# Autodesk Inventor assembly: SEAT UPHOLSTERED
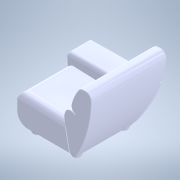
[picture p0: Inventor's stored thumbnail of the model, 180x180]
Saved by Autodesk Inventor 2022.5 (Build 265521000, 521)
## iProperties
Created: 2025-08
Part Number: SEAT UPHOLSTERED
Material: Generic
Document SubType Name: Modeling
Designer: Mark.Glazzard
Density: 1 g/cm^3
Appearance: Default
Author: Mark.Glazzard
Revision Number: ANY
Part Number: 1SG-0001 Arm Subassembly_UPHOLSTERED
Document SubType Name: Assembly
Part Number: ARM UPHOLSTERED
Part Number: 1SG-0001 Seat Subassembly_UPHOLSTERED
Part Number: 1SG-0001 Snug with Right Arm_Upholstered
Description: STEP AP214
Title: 1SG-0001 Snug with Right Arm_Upholstered.STEP
Sending System: SolidWorks 2025
Preprocessor: SwSTEP 2.0
Part Number: 1SG-0001 Back Subassembly_UPHOLSTERED
Part Number: BACK UPHOLSTERED
Part Number: PCM5592 - Snug Feet (Rev E)
Part Number: 1SG-0001 Snug with Right Arm (Simplify) 2022
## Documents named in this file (9)
- **S:\DRAWINGS\DRAWING OFFICE ONLY\WIP\1298 Snug with Arm\1SG-0001-01 Snug with Right Arm\Marketing and Sales Files\Simplified Inventor\1SG-0001 Snug with Right Arm (Simplify) 2022.iam*LocalDocs*xAaaaqebaAaaaaaaaAaaaapvl5e*SEAT UPHOLSTERED.ipt
- **S:\DRAWINGS\DRAWING OFFICE ONLY\WIP\1298 Snug with Arm\1SG-0001-01 Snug with Right Arm\Marketing and Sales Files\Simplified Inventor\1SG-0001 Snug with Right Arm (Simplify) 2022.iam*LocalDocs*xAaaaq0aaAaaaaaaaAaaaqzquAf*1SG-0001 Arm Subassembly_UPHOLSTERED.iam
- **S:\DRAWINGS\DRAWING OFFICE ONLY\WIP\1298 Snug with Arm\1SG-0001-01 Snug with Right Arm\Marketing and Sales Files\Simplified Inventor\1SG-0001 Snug with Right Arm (Simplify) 2022.iam*LocalDocs*xAaaaadaaAaaaaaaaAaaaqlp0Ea*ARM UPHOLSTERED.ipt
- **S:\DRAWINGS\DRAWING OFFICE ONLY\WIP\1298 Snug with Arm\1SG-0001-01 Snug with Right Arm\Marketing and Sales Files\Simplified Inventor\1SG-0001 Snug with Right Arm (Simplify) 2022.iam*LocalDocs*xAaaaq3caAaaaaaaaAaaaa3sn1a*1SG-0001 Seat Subassembly_UPHOLSTERED.iam
- **S:\DRAWINGS\DRAWING OFFICE ONLY\WIP\1298 Snug with Arm\1SG-0001-01 Snug with Right Arm\Marketing and Sales Files\Simplified Inventor\1SG-0001 Snug with Right Arm (Simplify) 2022.iam*LocalDocs*xAaaaq1caAaaaaaaaAaaaanuyJe*1SG-0001 Snug with Right Arm_Upholstered.iam
- **S:\DRAWINGS\DRAWING OFFICE ONLY\WIP\1298 Snug with Arm\1SG-0001-01 Snug with Right Arm\Marketing and Sales Files\Simplified Inventor\1SG-0001 Snug with Right Arm (Simplify) 2022.iam*LocalDocs*xAaaaqndaAaaaaaaaAaaaqfvyLc*1SG-0001 Back Subassembly_UPHOLSTERED.iam
- **S:\DRAWINGS\DRAWING OFFICE ONLY\WIP\1298 Snug with Arm\1SG-0001-01 Snug with Right Arm\Marketing and Sales Files\Simplified Inventor\1SG-0001 Snug with Right Arm (Simplify) 2022.iam*LocalDocs*xAaaaqscaAaaaaaaaAaaaq5lf1f*PCM5592 - Snug Feet (Rev E).ipt
- **S:\DRAWINGS\DRAWING OFFICE ONLY\WIP\1298 Snug with Arm\1SG-0001-01 Snug with Right Arm\Marketing and Sales Files\Simplified Inventor\1SG-0001 Snug with Right Arm (Simplify) 2022.iam*LocalDocs*xAaaaqmbaAaaaaaaaAaaaqwtbPc*BACK UPHOLSTERED.ipt
- S:\DRAWINGS\DRAWING OFFICE ONLY\WIP\1298 Snug with Arm\1SG-0001-01 Snug with Right Arm\Marketing and Sales Files\Simplified Inventor\1SG-0001 Snug with Right Arm (Simplify) 2022.iam
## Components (1 placed, 1 different names)
1. 1SG-0001 Snug with Right Arm_Upholstered:1 [sub-assembly]
